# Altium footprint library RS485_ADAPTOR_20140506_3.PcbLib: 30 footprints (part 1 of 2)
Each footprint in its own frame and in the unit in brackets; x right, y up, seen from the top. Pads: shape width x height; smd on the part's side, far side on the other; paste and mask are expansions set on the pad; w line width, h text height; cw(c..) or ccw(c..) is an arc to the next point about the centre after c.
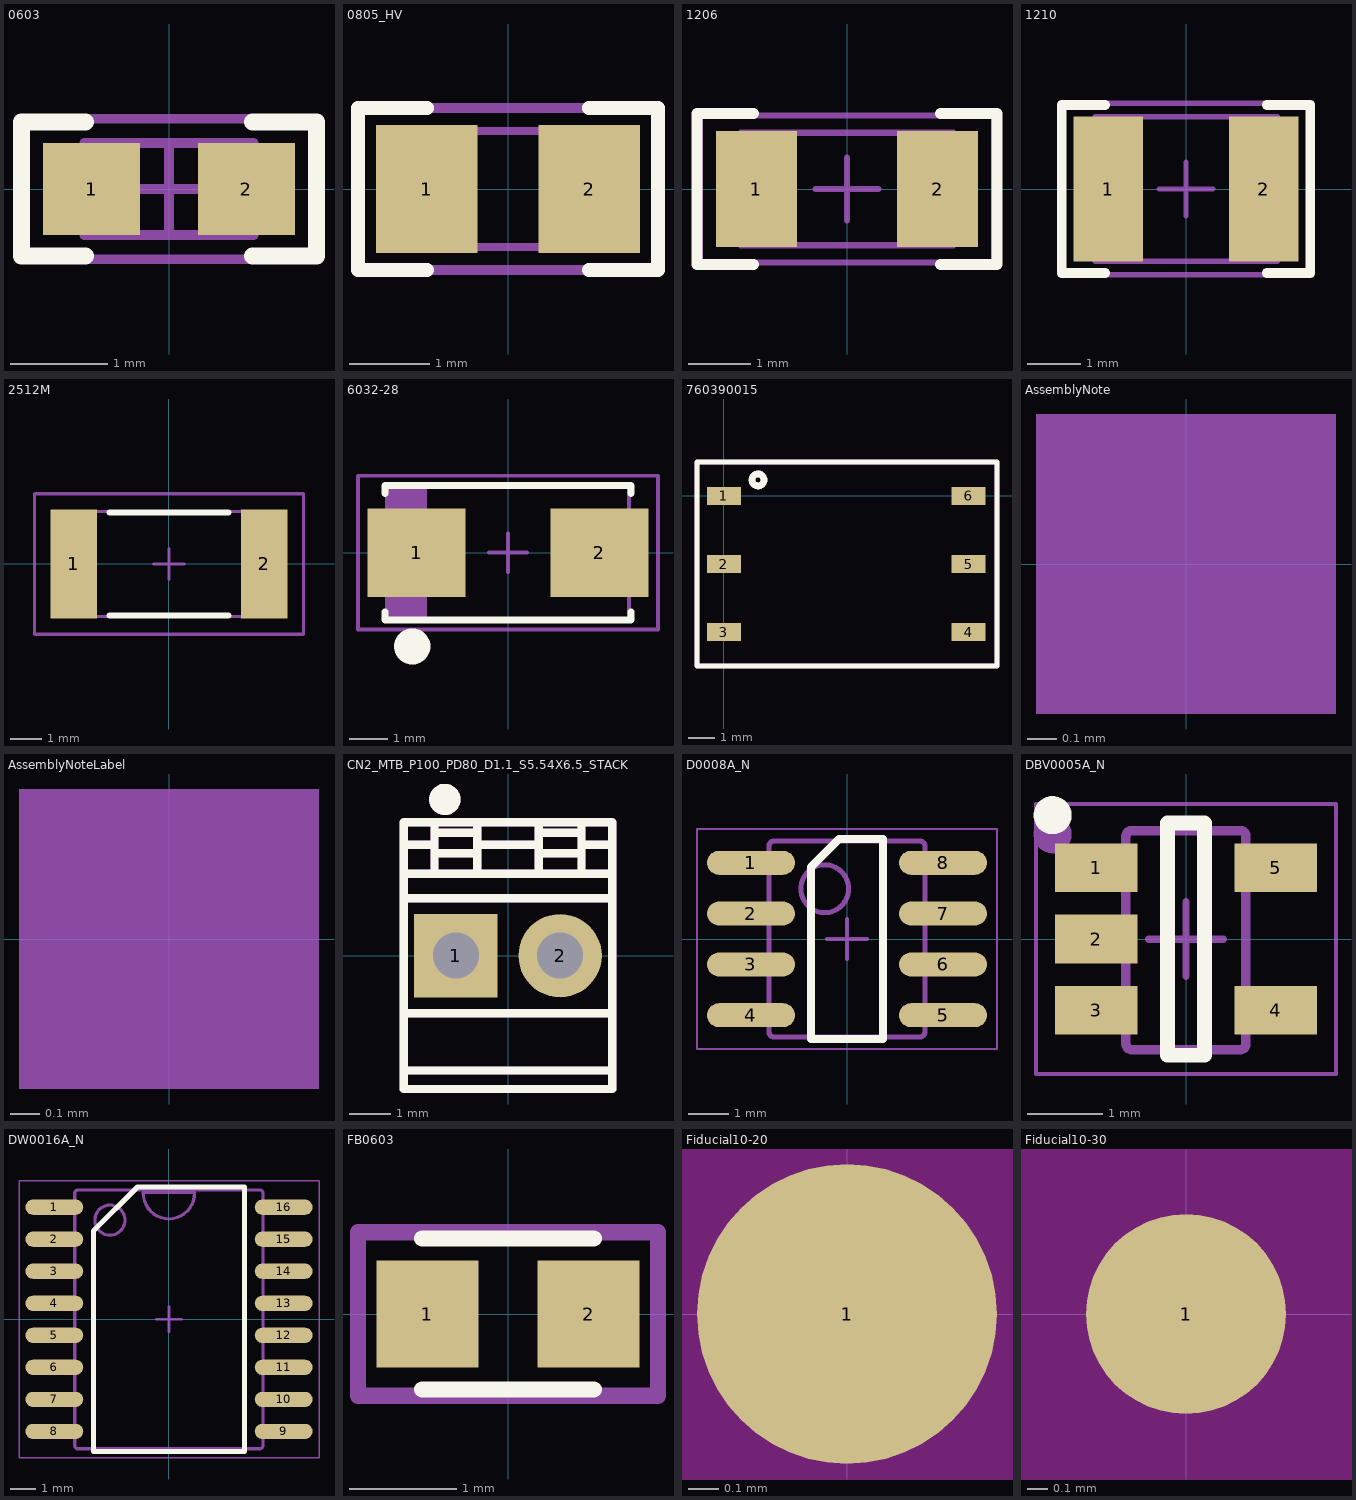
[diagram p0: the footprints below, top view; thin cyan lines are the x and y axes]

## 0603 [mm]
height 3
pads (2):
  rect 1x0.95 smd: 1(-0.8,0) 2(0.8,0)
Top Overlay:
  lines w0.178: -0.864,-0.691 -1.524,-0.691 -1.524,0.693 -0.864,0.693 ; 0.864,-0.691 1.524,-0.691 1.524,0.693 0.864,0.693
Mechanical 5:
  lines w0.1: -1.55,-0.725 1.55,-0.725 1.55,0.725 -1.55,0.725 -1.55,-0.725
  text ".Designator" at -0.762,-0.356 h0.76
Mechanical 13:
  lines w0.1: -0.55,-0.475 -0.55,0.475 ; 0.55,-0.475 0.55,0.475 ; -0.875,-0.475 -0.875,0.475 0.875,0.475 0.875,-0.475 -0.875,-0.475
Mechanical 15:
  lines w0.1: -0.475,0 0.475,0 ; 0,-0.475 0,0.475 ; -1.55,-0.725 -1.55,0.725 1.55,0.725 1.55,-0.725 -1.55,-0.725
3D body: height 0.85, standoff 0, extent 0.551,-0.474 0.874,0.474
3D body: height 0.85, standoff 0, extent -0.549,-0.474 0.549,0.474
3D body: height 0.85, standoff 0, extent -0.874,-0.474 -0.551,0.474

## 0805_HV [mil] "0805 with 30mil clearance between pads"
height 43.31
pads (2):
  rect 50x63 smd: 1(-40,0) 2(40,0)
Top Overlay:
  lines w7: -40,-40 -74,-40 -74,0 -74,40 -40,40 ; 40,-40 74,-40 74,0 74,40 40,40
Mechanical 5:
  lines w5: -74,-40 -74,40 74,40 74,-40 -74,-40
  text ".Designator" at 19,15 h30
Mechanical 13:
  lines w3.94: -25.59,-28.54 -25.59,28.54 ; 25.59,-28.54 25.59,28.54 ; -43.31,-28.54 43.31,-28.54 43.31,28.54 -43.31,28.54 -43.31,-28.54
3D body: height 43.31, standoff 0, extent -43.29,-28.52 -25.61,28.52
3D body: height 43.31, standoff 0, extent -25.57,-28.52 25.57,28.52
3D body: height 43.31, standoff 0, extent 25.61,-28.52 43.29,28.52

## 1206 [mm] "1206 from SM-752 data"
height 1.35
pads (2):
  rect 1.3x1.85 smd: 1(-1.45,0) 2(1.45,0)
Top Overlay:
  lines w0.178: -1.5,-1.21 -2.4,-1.21 -2.4,1.21 -1.5,1.21 ; 1.5,-1.21 2.4,-1.21 2.4,1.21 1.5,1.21
Mechanical 5:
  lines w0.1: -1.7,-0.9 -1.7,0.9 1.7,0.9 1.7,-0.9 -1.7,-0.9
  text ".Designator" at -1.475,-0.4 h0.81
Mechanical 13:
  lines w0.1: -1.2,-0.9 -1.2,0.9 ; 1.2,-0.9 1.2,0.9 ; -1.7,-0.9 -1.7,0.9 1.7,0.9 1.7,-0.9 -1.7,-0.9
Mechanical 15:
  lines w0.1: -0.5,0 0.5,0 ; 0,-0.5 0,0.5 ; -2.35,-1.175 -2.35,1.175 2.35,1.175 2.35,-1.175 -2.35,-1.175
3D body: height 1.35, standoff 0, extent 1.201,-0.899 1.699,0.899
3D body: height 1.35, standoff 0, extent -1.199,-0.899 1.199,0.899
3D body: height 1.35, standoff 0, extent -1.699,-0.899 -1.201,0.899

## 1210 [mm]
height 3
pads (2):
  rect 1.3x2.7 smd: 1(-1.45,0) 2(1.45,0)
Top Overlay:
  lines w0.178: -1.511,-1.568 -2.316,-1.568 -2.316,1.568 -1.511,1.568 ; 1.511,-1.568 2.316,-1.568 2.316,1.568 1.511,1.568
Mechanical 5:
  lines w0.1: -1.7,-1.35 -1.7,1.35 1.7,1.35 1.7,-1.35 -1.7,-1.35
  text ".Designator" at -1.4,-0.375 h0.76
Mechanical 13:
  lines w0.1: -1.2,-1.35 -1.2,1.35 ; 1.2,-1.35 1.2,1.35 ; -1.7,-1.35 1.7,-1.35 1.7,1.35 -1.7,1.35 -1.7,-1.35
Mechanical 15:
  lines w0.1: -0.5,0 0.5,0 ; 0,-0.5 0,0.5 ; -2.35,-1.6 2.35,-1.6 2.35,1.6 -2.35,1.6 -2.35,-1.6
3D body: height 1.35, standoff 0, extent 1.201,-1.349 1.699,1.349
3D body: height 1.35, standoff 0, extent -1.199,-1.349 1.199,1.349
3D body: height 1.35, standoff 0, extent -1.699,-1.349 -1.201,1.349

## 2512M [mm] "Chip Resistor, Body 6.3x3.2mm, IPC Low Density"
height 0.71
pads (2):
  rect 1.5x3.5 smd: 1(-3.05,0) 2(3.05,0)
Top Overlay:
  lines w0.2: -1.9,-1.65 1.9,-1.65 ; -1.9,1.65 1.9,1.65
Mechanical 5:
  lines w0.1: -3.225,-1.675 3.225,-1.675 3.225,1.675 -3.225,1.675 -3.225,-1.675
  text ".Designator" at -1.85,-0.5 h0.76
Mechanical 13:
  lines w0.1: -2.463,-1.675 -2.463,1.675 ; 2.463,-1.675 2.463,1.675 ; -3.225,-1.675 3.225,-1.675 3.225,1.675 -3.225,1.675 -3.225,-1.675
Mechanical 15:
  lines w0.1: -0.5,0 0.5,0 ; 0,-0.5 0,0.5 ; -4.3,-2.25 4.3,-2.25 4.3,2.25 -4.3,2.25 -4.3,-2.25
3D body: height 0.71, standoff 0, extent -3.224,-1.674 -2.464,1.674
3D body: height 0.71, standoff 0, extent -2.462,-1.674 2.462,1.674
3D body: height 0.71, standoff 0, extent 2.464,-1.674 3.224,1.674

## 6032-28 [mm]
height 3
pads (2):
  rect 2.55x2.3 smd: 1(-2.375,0) 2(2.375,0)
Top Overlay:
  circle w0.635: c-2.489,-2.438 r0.152
  lines w0.178: -3.2,-1.539 -3.2,-1.75 3.2,-1.75 3.2,-1.539 ; -3.2,1.539 -3.2,1.75 3.2,1.75 3.2,1.539
Mechanical 5:
  rectangle: -3.15,-1.75 -2.15,1.75
  lines w0.1: -2.15,-1.75 -2.15,1.75 ; -3.15,-1.75 -3.15,1.75 3.15,1.75 3.15,-1.75 -3.15,-1.75
  text ".Designator" at 0.813,0.559 h0.76
Mechanical 15:
  lines w0.1: -0.5,0 0.5,0 ; 0,-0.5 0,0.5 ; -3.9,-2 3.9,-2 3.9,2 -3.9,2 -3.9,-2
3D body: height 2.8, standoff 0, extent -3.15,-1.75 3.15,1.75
3D body: height 2.8, standoff 2.8, extent -3.149,-1.749 -2.151,1.749

## 760390015 [mm]
height 3
pads (6):
  rect 1.27x0.66 smd: 1(0,0) 2(0,-2.54) 3(0,-5.08) 4(9.14,-5.08) 5(9.14,-2.54) 6(9.14,0)
Top Overlay:
  circle w0.254: c1.276,0.6 r0.224
  lines w0.2: -1,-6.35 10.2,-6.35 10.2,1.27 -1,1.27 -1,-6.35
Mechanical 5:
  circle w0.254: c1.276,0.6 r0.224
  lines w0.2: -1,-6.35 -1,1.27 10.2,1.27 10.2,-6.35 -1,-6.35
  text ".designator" at 1.27,2.032 h0.76
3D body: height 4.2, standoff 0.2, extent -1,-6.4 10.2,1.2

## AssemblyNote [mm] "Assembly Note"
Mechanical 5:
  rectangle: -0.508,-0.508 0.508,0.508
  text ".Designator" at -4.191,-0.508 h0.76
  text ".Comment" at 1.143,-0.508 h1.02

## AssemblyNoteLabel [mm] "Assembly Note for PCB Labels"
Mechanical 5:
  rectangle: -0.508,-0.508 0.508,0.508
  text ".Designator" at -4.191,-0.508 h0.76
  text "Install label in silkscreened box after final wash.  Text shall be 8 pt font.  Text shall be per the Label Table in the PDF schematic." at 1.143,-0.508 h1.02

## CN2_MTB_P100_PD80_D1.1_S5.54X6.5_STACK [mil]
height 118.11
pads (2):
  rect 80x80 / inner round 80 / far side rect 80x80 hole 44: 1(-50,0)
  round 80 hole 44: 2(50,0)
Top Overlay:
  circle w10: c-60.63,149.95 r10
  circle w10: c-60.63,149.95 r5
  lines w8: -100,-110.24 100,-110.24 ; -100,-55.12 100,-55.12 ; -100,55.12 100,55.12 ; -100,78.74 100,78.74 ; -100,106.3 -70.87,106.3 ; -70.47,78.74 -70.47,127.95 ; -70.47,98.43 -31.5,98.43 ; -70.47,118.11 -31.5,118.11 ; -29.53,78.74 -29.53,127.95 ; -27.56,106.3 27.56,106.3 ; 29.53,78.74 29.53,127.95 ; 31.5,98.43 66.93,98.43 ; 31.5,118.11 66.93,118.11 ; 70.47,78.74 70.47,127.95 ; 70.87,106.3 100,106.3 ; -100,-127.95 100,-127.95 100,127.95 -100,127.95 -100,-127.95
  text ".designator" at -15,150 h40
Mechanical 5:
  circle w10: c-60.63,149.95 r5
  circle w10: c-60.63,149.95 r10
  lines w8: -100,-110.24 100,-110.24 ; -100,-55.12 100,-55.12 ; -100,55.12 100,55.12 ; -100,78.74 100,78.74 ; -100,106.3 -70.87,106.3 ; -70.47,78.74 -70.47,127.95 ; -70.47,98.43 -31.5,98.43 ; -70.47,118.11 -31.5,118.11 ; -29.53,78.74 -29.53,127.95 ; -27.56,106.3 27.56,106.3 ; 29.53,78.74 29.53,127.95 ; 31.5,98.43 66.93,98.43 ; 31.5,118.11 66.93,118.11 ; 70.47,78.74 70.47,127.95 ; 70.87,106.3 100,106.3 ; -100,-127.95 -100,127.95 100,127.95 100,-127.95 -100,-127.95
  text ".designator" at -15,150 h30

## D0008A_N [mm]
height 3
pads (8):
  oval 2.2x0.6 smd: 1(-2.4,1.905) 2(-2.4,0.635) 3(-2.4,-0.635) 4(-2.4,-1.905) 5(2.4,-1.905) 6(2.4,-0.635) 7(2.4,0.635) 8(2.4,1.905)
Top Overlay:
  lines w0.2: -0.9,-2.5 -0.9,1.8 -0.2,2.5 0.9,2.5 0.9,-2.5 -0.9,-2.5
Mechanical 5:
  lines w0.127: -2.375,-2.095 -1.995,-2.095 -1.952,-2.095 -1.952,-1.715 -1.995,-1.715 -2.375,-1.715 ; -2.375,-2.095 -2.589,-2.095 -3.002,-2.095 -3.002,-1.715 -2.589,-1.715 -2.375,-1.715 ; -2.375,-2.095 -2.375,-1.715 ; -2.375,-0.825 -1.995,-0.825 -1.952,-0.825 -1.952,-0.445 -1.995,-0.445 -2.375,-0.445 ; -2.375,-0.825 -2.589,-0.825 -3.002,-0.825 -3.002,-0.445 -2.589,-0.445 -2.375,-0.445 ; -2.375,-0.825 -2.375,-0.445 ; -2.375,0.445 -1.995,0.445 -1.952,0.445 -1.952,0.825 -1.995,0.825 -2.375,0.825 ; -2.375,0.445 -2.589,0.445 -3.002,0.445 -3.002,0.825 -2.589,0.825 -2.375,0.825 ; -2.375,0.445 -2.375,0.825 ; -2.375,1.715 -1.995,1.715 -1.952,1.715 -1.952,2.095 -1.995,2.095 -2.375,2.095 ; -2.375,1.715 -2.589,1.715 -3.002,1.715 -3.002,2.095 -2.589,2.095 -2.375,2.095 ; -2.375,1.715 -2.375,2.095 ; -0.332,-2.45 -1.825,-2.45 -1.826,-2.45 cw(c-1.825,-2.323) -1.952,-2.324 -1.952,-2.323 -1.952,2.323 -1.952,2.324 cw(c-1.825,2.323) -1.826,2.45 -1.825,2.45 -0.332,2.45 ; -0.332,-2.45 -0.182,-2.45 ; -0.332,-2.45 -0.182,-2.45 ; -0.332,2.45 -0.182,2.45 ; -0.332,2.45 -0.182,2.45 ; -0.182,-2.45 0.178,-2.45 ; -0.182,2.45 0.178,2.45 ; 0.178,-2.45 0.328,-2.45 ; 0.178,-2.45 0.328,-2.45 ; 0.178,2.45 0.328,2.45 ; 0.178,2.45 0.328,2.45 ; 0.328,-2.45 1.821,-2.45 1.822,-2.45 ccw(c1.821,-2.323) 1.948,-2.324 1.948,-2.323 1.948,2.323 1.948,2.324 ccw(c1.821,2.323) 1.822,2.45 1.821,2.45 0.328,2.45 ; 2.371,-2.095 2.585,-2.095 2.998,-2.095 2.998,-1.715 2.585,-1.715 2.371,-1.715 ; 2.371,-2.095 1.991,-2.095 1.948,-2.095 1.948,-1.715 1.991,-1.715 2.371,-1.715 ; 2.371,-2.095 2.371,-1.715 ; 2.371,-0.825 2.585,-0.825 2.998,-0.825 2.998,-0.445 2.585,-0.445 2.371,-0.445 ; 2.371,-0.825 1.991,-0.825 1.948,-0.825 1.948,-0.445 1.991,-0.445 2.371,-0.445 ; 2.371,-0.825 2.371,-0.445 ; 2.371,0.445 2.585,0.445 2.998,0.445 2.998,0.825 2.585,0.825 2.371,0.825 ; 2.371,0.445 1.991,0.445 1.948,0.445 1.948,0.825 1.991,0.825 2.371,0.825 ; 2.371,0.445 2.371,0.825 ; 2.371,1.715 2.585,1.715 2.998,1.715 2.998,2.095 2.585,2.095 2.371,2.095 ; 2.371,1.715 1.991,1.715 1.948,1.715 1.948,2.095 1.991,2.095 2.371,2.095 ; 2.371,1.715 2.371,2.095 ; -0.555,0.659 cw(c-0.555,1.256) -0.555,1.853 cw(c-0.555,1.256) -0.555,0.659
  text ".Designator" at -0.914,-0.813 h0.76
Mechanical 15:
  lines w0.05: -3.75,-2.75 -3.75,2.75 3.75,2.75 3.75,-2.75 -3.75,-2.75
  lines w0.1: -0.5,0 0.5,0 ; 0,-0.5 0,0.5
3D body: height 1.63, standoff 0, extent -3,-2.45 3,2.45

## DBV0005A_N [mm]
height 3
pads (5):
  rect 1.1x0.65 smd: 1(-1.2,0.95) 2(-1.2,0) 3(-1.2,-0.95) 4(1.2,-0.95) 5(1.2,0.95)
Top Overlay:
  circle w0.254: c-1.778,1.651 r0.127
  lines w0.2: -0.25,-1.55 0.25,-1.55 0.25,1.55 -0.25,1.55 -0.25,-1.55
Mechanical 5:
  circle w0.254: c-1.778,1.397 r0.127
  lines w0.127: -0.801,1.371 cw(c-0.725,1.37) -0.725,1.446 ; -0.801,1.37 -0.801,-1.399 -0.801,-1.4 ccw(c-0.725,-1.399) -0.725,-1.475 ; -0.801,1.37 -0.801,1.371 ; -0.725,-1.475 -0.725,-1.475 ; -0.725,-1.475 0.723,-1.475 0.724,-1.475 ccw(c0.723,-1.399) 0.799,-1.4 0.799,-1.399 0.799,1.37 ; -0.725,1.446 0.723,1.446 0.724,1.446 cw(c0.723,1.37) 0.799,1.371 ; -0.725,1.446 -0.725,1.446 ; 0.799,1.37 0.799,1.371 ; -1.423,-1.167 -1.199,-1.167 -1.105,-1.167 -1.088,-1.167 -0.835,-1.167 -0.801,-1.167 -0.801,-0.767 -0.835,-0.767 -1.088,-0.767 -1.105,-0.767 -1.199,-0.767 -1.423,-0.767 -1.423,-1.167 ; -1.423,-0.215 -1.199,-0.215 -1.105,-0.215 -1.088,-0.215 -0.835,-0.215 -0.801,-0.215 -0.801,0.186 -0.835,0.186 -1.088,0.186 -1.105,0.186 -1.199,0.186 -1.423,0.186 -1.423,-0.215 ; -1.423,0.738 -1.199,0.738 -1.105,0.738 -1.088,0.738 -0.835,0.738 -0.801,0.738 -0.801,1.138 -0.835,1.138 -1.088,1.138 -1.105,1.138 -1.199,1.138 -1.423,1.138 -1.423,0.738 ; 0.799,-1.167 0.799,-0.767 0.834,-0.767 1.087,-0.767 1.103,-0.767 1.198,-0.767 1.422,-0.767 1.422,-1.167 1.198,-1.167 1.103,-1.167 1.087,-1.167 0.834,-1.167 0.799,-1.167 ; 0.799,0.738 0.799,1.138 0.834,1.138 1.087,1.138 1.103,1.138 1.198,1.138 1.422,1.138 1.422,0.738 1.198,0.738 1.103,0.738 1.087,0.738 0.834,0.738 0.799,0.738
  text ".Designator" at 0.254,-1.143 h0.76
Mechanical 15:
  lines w0.05: -2,-1.8 -2,1.8 2,1.8 2,-1.8 -2,-1.8
  lines w0.1: -0.5,0 0.5,0 ; 0,-0.5 0,0.5
3D body: height 1.08, standoff -0.01, extent -1.422,-1.461 1.422,1.46

## DW0016A_N [mm] "SOIC, 16-Leads, Body 10.3x7.5mm, Pitch 1.27mm, IPC Medium Density"
height 2.64
pads (16):
  oval 2.3x0.6 smd: 1(-4.55,4.445) 2(-4.55,3.175) 3(-4.55,1.905) 4(-4.55,0.635) 5(-4.55,-0.635) 6(-4.55,-1.905) 7(-4.55,-3.175) 8(-4.55,-4.445) 9(4.55,-4.445) 10(4.55,-3.175) 11(4.55,-1.905) 12(4.55,-0.635) 13(4.55,0.635) 14(4.55,1.905) 15(4.55,3.175) 16(4.55,4.445)
Top Overlay:
  lines w0.2: -3,-5.25 -3,3.5 -1.25,5.25 3,5.25 3,-5.25 -3,-5.25
Mechanical 5:
  drawing of 193 lines, arcs and shapes, not listed
  text ".Designator" at -0.686,-0.533 h0.76
Mechanical 15:
  lines w0.05: -5.95,-5.5 -5.95,5.5 5.95,5.5 5.95,-5.5 -5.95,-5.5
  lines w0.1: -0.5,0 0.5,0 ; 0,-0.5 0,0.5
3D body: height 2.5, standoff -0.04, extent -5.144,-5.131 5.143,5.131

## FB0603 [mm]
height 3
pads (2):
  rect 0.95x1 smd: 1(-0.75,0) 2(0.75,0)
Top Overlay:
  lines w0.152: -0.8,-0.703 0.8,-0.703 ; -0.8,0.703 0.8,0.703
Mechanical 5:
  lines w0.152: -1.397,-0.762 1.397,-0.762 1.397,0.127 1.397,0.762 -1.397,0.762 -1.397,-0.762
  text ".designator" at -1.143,-0.381 h0.76
Mechanical 15:
  lines w0.025: -0.8,-0.4 -0.8,0.4 ; 0.8,-0.4 0.8,0.4
  lines w0.1: -0.8,-0.4 -0.8,0.4

## Fiducial10-20 [mm]
height 3
pads (1):
  round 1 smd paste-0.5 mask+0.5: 1(0,0)
Top Layer keep-out:
  circle w1.178: c0,0 r0.5

## Fiducial10-30 [mm]
height 3
pads (1):
  round 1 smd paste-0.5 mask+1: 1(0,0)
Top Layer keep-out:
  circle w1.678: c0,0 r0.75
